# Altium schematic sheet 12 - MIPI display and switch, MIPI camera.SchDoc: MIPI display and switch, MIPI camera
size A3; PageSetup: Record=PageOptions¦CenterHorizontal=True¦CenterVertical=True¦PrintScale=0.70¦XCorrection=1.00¦YCorrection=1.00¦PrintKind=0¦BorderSize=5000000¦LeftOffset=0¦BottomOffset=0¦Orientation=2¦PaperLength=4200¦PaperWidth=2970¦Scale=100¦PaperSource=7¦PrintQuality=600¦MediaType=1¦DitherType=10¦PaperKind=A4¦PrintScaleMode=1; Author: Juan Anzola; SheetNumber: 12; SheetTotal: 21
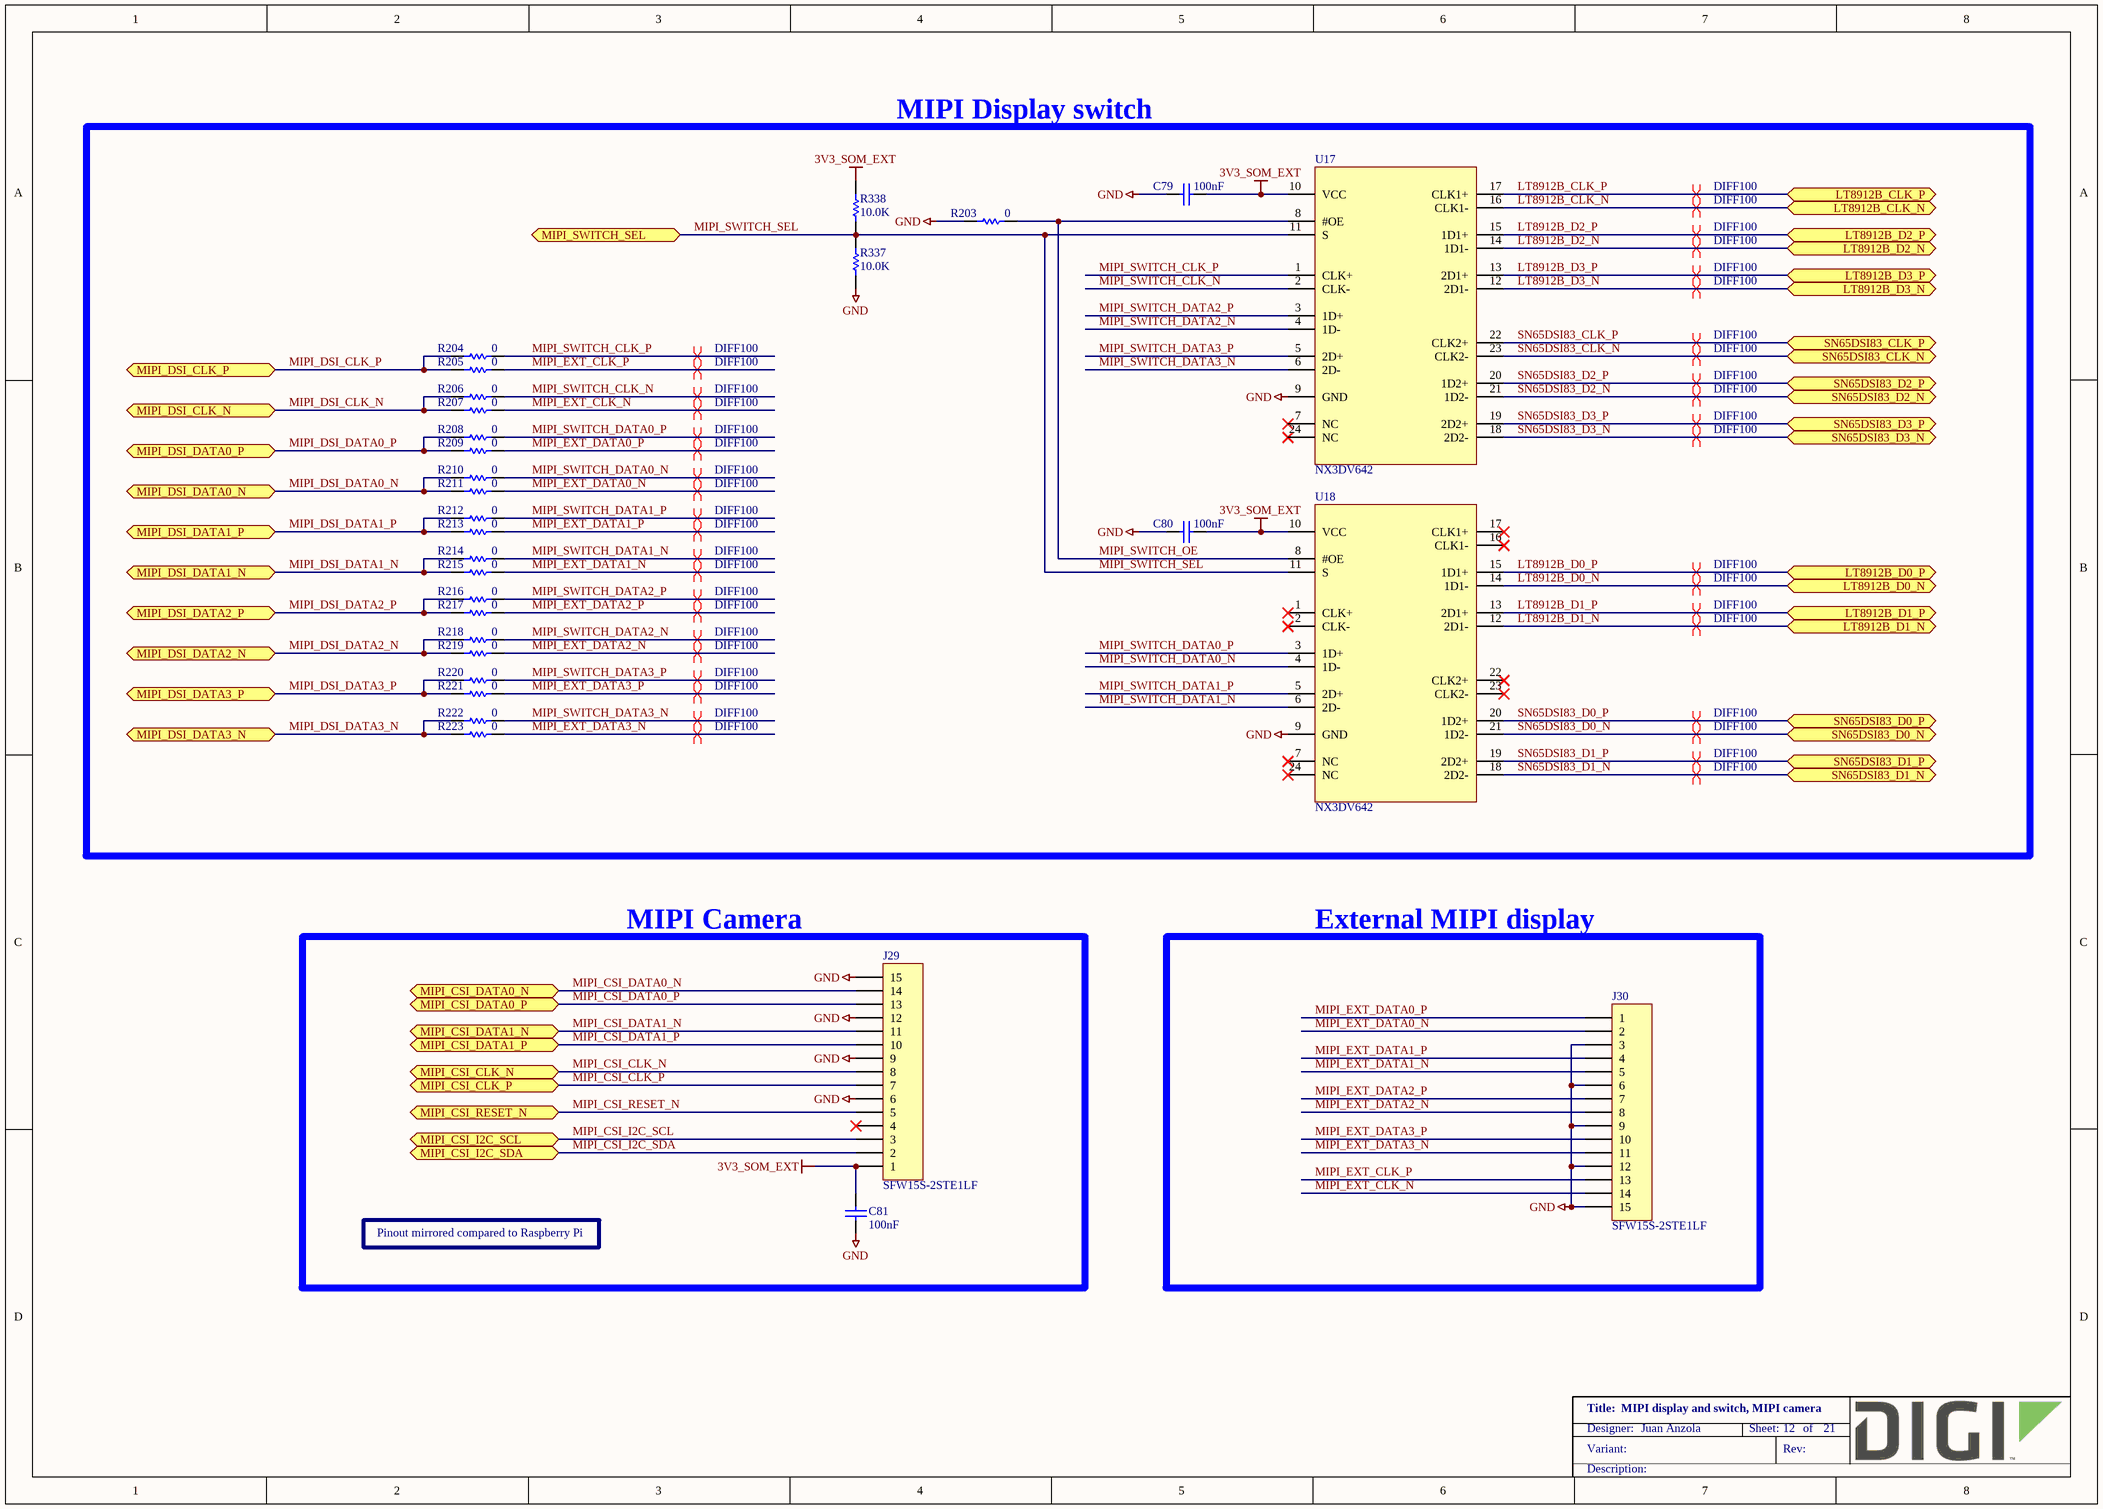
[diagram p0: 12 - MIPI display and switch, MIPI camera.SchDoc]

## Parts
C79  100nF  [CAPC1005X55N]
C80  100nF  [CAPC1005X55N]
C81  100nF  [CAPC1005X55N]
J29  SFW15S-2STE1LF  [FCI_SFW15S-2STE1LF]
J30  SFW15S-2STE1LF  [FCI_SFW15S-2STE1LF]
R203  0  [RESC1609X55N]
R204  0  [RESC1609X55N]
R205  0  [RESC1609X55N]
R206  0  [RESC1609X55N]
R207  0  [RESC1609X55N]
R208  0  [RESC1609X55N]
R209  0  [RESC1609X55N]
R210  0  [RESC1609X55N]
R211  0  [RESC1609X55N]
R212  0  [RESC1609X55N]
R213  0  [RESC1609X55N]
R214  0  [RESC1609X55N]
R215  0  [RESC1609X55N]
R216  0  [RESC1609X55N]
R217  0  [RESC1609X55N]
R218  0  [RESC1609X55N]
R219  0  [RESC1609X55N]
R220  0  [RESC1609X55N]
R221  0  [RESC1609X55N]
R222  0  [RESC1609X55N]
R223  0  [RESC1609X55N]
R337  10.0K  [RESC1005X40N]
R338  10.0K  [RESC1005X40N]
U17  NX3DV642  [QFN40P340X250X50-24N]
U18  NX3DV642  [QFN40P340X250X50-24N]

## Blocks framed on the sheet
MIPI Display switch: C79 C80 R203-R223 R337 R338 U17 U18
MIPI Camera: C81 J29
External MIPI display: J30

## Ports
LT8912B_CLK_N (bidir), LT8912B_CLK_P (bidir), LT8912B_D0_N (bidir), LT8912B_D0_P (bidir), LT8912B_D1_N (bidir), LT8912B_D1_P (bidir), LT8912B_D2_N (bidir), LT8912B_D2_P (bidir), LT8912B_D3_N (bidir), LT8912B_D3_P (bidir), MIPI_CSI_CLK_N (bidir), MIPI_CSI_CLK_P (bidir), MIPI_CSI_DATA0_N (bidir), MIPI_CSI_DATA0_P (bidir), MIPI_CSI_DATA1_N (bidir), MIPI_CSI_DATA1_P (bidir), MIPI_CSI_I2C_SCL (bidir), MIPI_CSI_I2C_SDA (bidir), MIPI_CSI_RESET_N (bidir), MIPI_DSI_CLK_N (bidir), MIPI_DSI_CLK_P (bidir), MIPI_DSI_DATA0_N (bidir), MIPI_DSI_DATA0_P (bidir), MIPI_DSI_DATA1_N (bidir), MIPI_DSI_DATA1_P (bidir), MIPI_DSI_DATA2_N (bidir), MIPI_DSI_DATA2_P (bidir), MIPI_DSI_DATA3_N (bidir), MIPI_DSI_DATA3_P (bidir), MIPI_SWITCH_SEL (bidir), SN65DSI83_CLK_N (bidir), SN65DSI83_CLK_P (bidir), SN65DSI83_D0_N (bidir), SN65DSI83_D0_P (bidir), SN65DSI83_D1_N (bidir), SN65DSI83_D1_P (bidir), SN65DSI83_D2_N (bidir), SN65DSI83_D2_P (bidir), SN65DSI83_D3_N (bidir), SN65DSI83_D3_P (bidir)

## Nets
3V3_SOM_EXT: C79.1 C80.1 C81.2 J29.1 R338.1 U17.10(VCC) U18.10(VCC)
GND: C79.2 C80.2 C81.1 J29.6 J29.9 J29.12 J29.15 J30.3 J30.6 J30.9 J30.12 J30.15 R203.1 R337.2 U17.9(GND) U18.9(GND)
LT8912B_CLK_N: U17.16(CLK1-) ; port LT8912B_CLK_N
LT8912B_CLK_P: U17.17(CLK1+) ; port LT8912B_CLK_P
LT8912B_D0_N: U18.14(1D1-) ; port LT8912B_D0_N
LT8912B_D0_P: U18.15(1D1+) ; port LT8912B_D0_P
LT8912B_D1_N: U18.12(2D1-) ; port LT8912B_D1_N
LT8912B_D1_P: U18.13(2D1+) ; port LT8912B_D1_P
LT8912B_D2_N: U17.14(1D1-) ; port LT8912B_D2_N
LT8912B_D2_P: U17.15(1D1+) ; port LT8912B_D2_P
LT8912B_D3_N: U17.12(2D1-) ; port LT8912B_D3_N
LT8912B_D3_P: U17.13(2D1+) ; port LT8912B_D3_P
MIPI_CSI_CLK_N: J29.8 ; port MIPI_CSI_CLK_N
MIPI_CSI_CLK_P: J29.7 ; port MIPI_CSI_CLK_P
MIPI_CSI_DATA0_N: J29.14 ; port MIPI_CSI_DATA0_N
MIPI_CSI_DATA0_P: J29.13 ; port MIPI_CSI_DATA0_P
MIPI_CSI_DATA1_N: J29.11 ; port MIPI_CSI_DATA1_N
MIPI_CSI_DATA1_P: J29.10 ; port MIPI_CSI_DATA1_P
MIPI_CSI_I2C_SCL: J29.3 ; port MIPI_CSI_I2C_SCL
MIPI_CSI_I2C_SDA: J29.2 ; port MIPI_CSI_I2C_SDA
MIPI_CSI_RESET_N: J29.5 ; port MIPI_CSI_RESET_N
MIPI_DSI_CLK_N: R206.1 R207.1 ; port MIPI_DSI_CLK_N
MIPI_DSI_CLK_P: R204.1 R205.1 ; port MIPI_DSI_CLK_P
MIPI_DSI_DATA0_N: R210.1 R211.1 ; port MIPI_DSI_DATA0_N
MIPI_DSI_DATA0_P: R208.1 R209.1 ; port MIPI_DSI_DATA0_P
MIPI_DSI_DATA1_N: R214.1 R215.1 ; port MIPI_DSI_DATA1_N
MIPI_DSI_DATA1_P: R212.1 R213.1 ; port MIPI_DSI_DATA1_P
MIPI_DSI_DATA2_N: R218.1 R219.1 ; port MIPI_DSI_DATA2_N
MIPI_DSI_DATA2_P: R216.1 R217.1 ; port MIPI_DSI_DATA2_P
MIPI_DSI_DATA3_N: R222.1 R223.1 ; port MIPI_DSI_DATA3_N
MIPI_DSI_DATA3_P: R220.1 R221.1 ; port MIPI_DSI_DATA3_P
MIPI_EXT_CLK_N: J30.14 R207.2
MIPI_EXT_CLK_P: J30.13 R205.2
MIPI_EXT_DATA0_N: J30.2 R211.2
MIPI_EXT_DATA0_P: J30.1 R209.2
MIPI_EXT_DATA1_N: J30.5 R215.2
MIPI_EXT_DATA1_P: J30.4 R213.2
MIPI_EXT_DATA2_N: J30.8 R219.2
MIPI_EXT_DATA2_P: J30.7 R217.2
MIPI_EXT_DATA3_N: J30.11 R223.2
MIPI_EXT_DATA3_P: J30.10 R221.2
MIPI_SWITCH_CLK_N: R206.2 U17.2(CLK-)
MIPI_SWITCH_CLK_P: R204.2 U17.1(CLK+)
MIPI_SWITCH_DATA0_N: R210.2 U18.4(1D-)
MIPI_SWITCH_DATA0_P: R208.2 U18.3(1D+)
MIPI_SWITCH_DATA1_N: R214.2 U18.6(2D-)
MIPI_SWITCH_DATA1_P: R212.2 U18.5(2D+)
MIPI_SWITCH_DATA2_N: R218.2 U17.4(1D-)
MIPI_SWITCH_DATA2_P: R216.2 U17.3(1D+)
MIPI_SWITCH_DATA3_N: R222.2 U17.6(2D-)
MIPI_SWITCH_DATA3_P: R220.2 U17.5(2D+)
MIPI_SWITCH_OE: R203.2 U17.8(#OE) U18.8(#OE)
MIPI_SWITCH_SEL: R337.1 R338.2 U17.11(S) U18.11(S) ; port MIPI_SWITCH_SEL
SN65DSI83_CLK_N: U17.23(CLK2-) ; port SN65DSI83_CLK_N
SN65DSI83_CLK_P: U17.22(CLK2+) ; port SN65DSI83_CLK_P
SN65DSI83_D0_N: U18.21(1D2-) ; port SN65DSI83_D0_N
SN65DSI83_D0_P: U18.20(1D2+) ; port SN65DSI83_D0_P
SN65DSI83_D1_N: U18.18(2D2-) ; port SN65DSI83_D1_N
SN65DSI83_D1_P: U18.19(2D2+) ; port SN65DSI83_D1_P
SN65DSI83_D2_N: U17.21(1D2-) ; port SN65DSI83_D2_N
SN65DSI83_D2_P: U17.20(1D2+) ; port SN65DSI83_D2_P
SN65DSI83_D3_N: U17.18(2D2-) ; port SN65DSI83_D3_N
SN65DSI83_D3_P: U17.19(2D2+) ; port SN65DSI83_D3_P

Not connected (* = marked no-connect by the designer): J29 4*; U17 7(NC)* 24(NC)*; U18 1(CLK+)* 2(CLK-)* 7(NC)* 16(CLK1-)* 17(CLK1+)* 22(CLK2+)* 23(CLK2-)* 24(NC)*

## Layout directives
differential pair; net class DIFF100: LT8912B_CLK_N, LT8912B_CLK_P, LT8912B_D0_N, LT8912B_D0_P, LT8912B_D1_N, LT8912B_D1_P, LT8912B_D2_N, LT8912B_D2_P, LT8912B_D3_N, LT8912B_D3_P, MIPI_EXT_CLK_N, MIPI_EXT_CLK_P, MIPI_EXT_DATA0_N, MIPI_EXT_DATA0_P, MIPI_EXT_DATA1_N, MIPI_EXT_DATA1_P, MIPI_EXT_DATA2_N, MIPI_EXT_DATA2_P, MIPI_EXT_DATA3_N, MIPI_EXT_DATA3_P, MIPI_SWITCH_CLK_N, MIPI_SWITCH_CLK_P, MIPI_SWITCH_DATA0_N, MIPI_SWITCH_DATA0_P, MIPI_SWITCH_DATA1_N, MIPI_SWITCH_DATA1_P, MIPI_SWITCH_DATA2_N, MIPI_SWITCH_DATA2_P, MIPI_SWITCH_DATA3_N, MIPI_SWITCH_DATA3_P, SN65DSI83_CLK_N, SN65DSI83_CLK_P, SN65DSI83_D0_N, SN65DSI83_D0_P, SN65DSI83_D1_N, SN65DSI83_D1_P, SN65DSI83_D2_N, SN65DSI83_D2_P, SN65DSI83_D3_N, SN65DSI83_D3_P

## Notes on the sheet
- Pinout mirrored compared to Raspberry Pi

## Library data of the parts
C79-C81 = 1000006: CAP 100nF 16V 10% X7R 0402; Part_Type: Capacitor; Manufacturer: Murata; Manufacturer_Part_Number: GRM155R71C104KA88D; Digi_PN: 14050552; Component_Life_Cycle_State: CAD Reviewed; Area: 0,95; Project: KITT; Tolerance: 10
J29 J30 = 1001866: CONN FFC FPC VERT 15POS 1MM SMD; Part_Type: Connector; Manufacturer: FCI; Digi_PN: 18000730; Component_Life_Cycle_State: Reviewed; Area: 128,76; Project: CCiMX6 SBC MFG TEST BOARD
R203-R223 = 1000208: RES 0.0 OHM 1/10W 0603; Part_Type: Resistor; Manufacturer: Panasonic - ECG; Manufacturer_Part_Number: ERJ-3GEY0R00V; Note: 13051103 = Digi No. for GE WDNU; Digi_PN: 13050568; Component_Life_Cycle_State: Reviewed; Area: 2,5; Voltage: 75V
R337 R338 = 1000537: RES 10.0K OHM 1/10W 1% 0402 SMD; Part_Type: Resistor; Manufacturer: Panasonic - ECG; Manufacturer_Part_Number: ERJ-2RKF1002X; Digi_PN: 13051084; Component_Life_Cycle_State: CAD Reviewed; Area: 0,95; Power_WV_SRF: 100
U17 U18 = 1002697: IC SWITCH TPDT DIFF XQFN24; Manufacturer: NXP Semiconductors; Digi_PN: 16000171; Component_Life_Cycle_State: Reviewed; Area: 17,35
